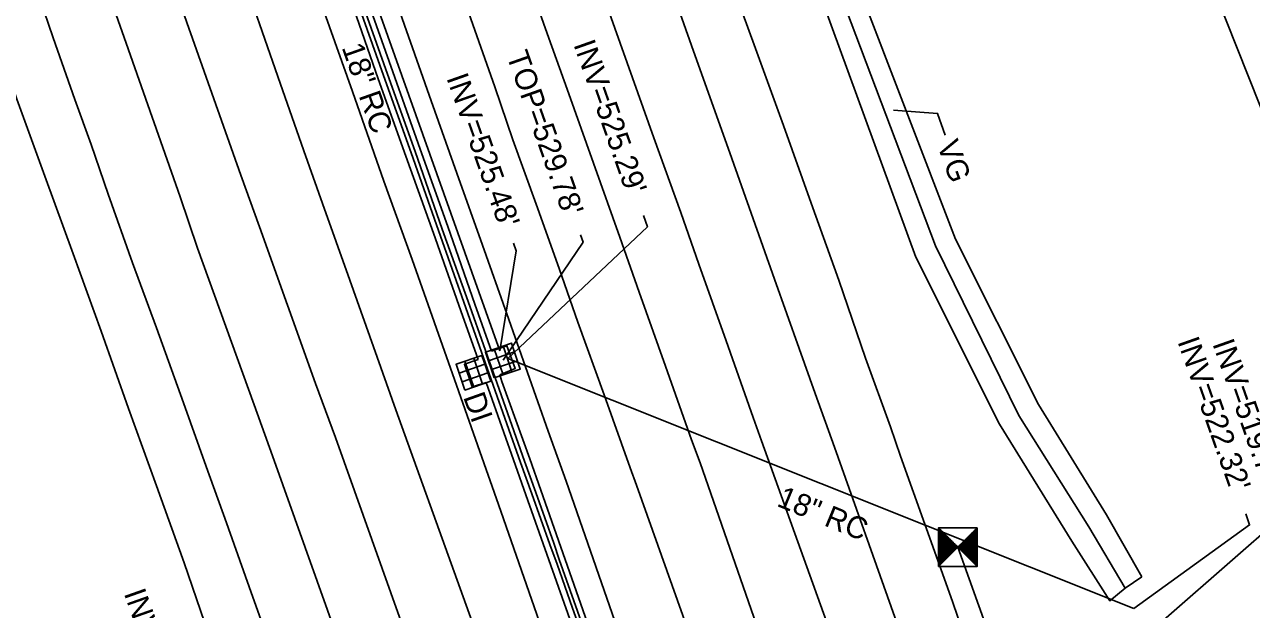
# Model space of a CAD drawing. Extents: x 2004847 to 2009016, y 1134161 to 1140101.
# Drawn here: x 2006823.5 to 2007047.7, y 1134296.2 to 1134403 of the extents above; entities that cross this region are included whole.
import ezdxf

# ---------------------------------------------------------------- set-up
doc = ezdxf.new("R2010")
doc.units = 0
for name, color, linetype in [('RD_EX_Conc', 7, 'Continuous'), ('RD_EX_DR_Inlet', 7, 'Continuous'), ('RD_EX_DR_Inlet_txCode', 7, 'Continuous'), ('RD_EX_DR_Pipe', 7, 'Continuous'), ('RD_EX_DR_Pipe_txCode', 7, 'Continuous'), ('RD_EX_Fence_Other', 7, 'Continuous'), ('RD_EX_Pavement_Markings', 7, 'Continuous'), ('RD_EX_Road', 7, 'Continuous'), ('RD_HC_Data', 7, 'Continuous'), ('RD_HC_Survey', 7, 'Continuous'), ('RD_Sketch1', 7, 'Continuous'), ('RD_Sketch3', 7, 'Continuous'), ('RD_SMD_Locator', 7, 'Continuous')]:
    doc.layers.add(name, color=color, linetype=linetype)

msp = doc.modelspace()

# ---------------------------------------------------------------- linework, layer by layer
at = {"layer": 'RD_EX_Conc'}
for points in [[(2007008.76, 1134333.65), (2006993.63, 1134363.82), (2006975.89, 1134409.97), (2006965.78, 1134441.02), (2006950.02, 1134485.15), (2006934.64, 1134528.55), (2006918.96, 1134572.55), (2006904.01, 1134614.93), (2006889.45, 1134656.34), (2006873.52, 1134701.79), (2006859.53, 1134740.78), (2006845, 1134783.14), (2006828.98, 1134829.04), (2006813.77, 1134872.83), (2006798.81, 1134915.62), (2006782.15, 1134963.38), (2006767.46, 1135005.24), (2006753.34, 1135046.25), (2006752.31, 1135048.89), (2006751.51, 1135051.2), (2006736.87, 1135093.18), (2006721.7, 1135136.82), (2006709.9, 1135170.59)], [(2007001.61, 1134330.02), (2006986.35, 1134360.57), (2006969.5, 1134406.75), (2006958.22, 1134438.26), (2006942.49, 1134482.23), (2006927.03, 1134526.16), (2006911.49, 1134569.75), (2006896.31, 1134613.04), (2006882.16, 1134653.08), (2006865.99, 1134699.12), (2006852.4, 1134738.21), (2006837.28, 1134781.15), (2006821.3, 1134826.88), (2006806.03, 1134870.56), (2006791.16, 1134913.28), (2006774.61, 1134960.65), (2006760.24, 1135002.17), (2006744.89, 1135045.85), (2006729.14, 1135091.12), (2006713.78, 1135134.81), (2006702.17, 1135168.35)], [(2006884.82, 1134408.14), (2006889.83, 1134394), (2006894.85, 1134379.86), (2006899.82, 1134365.69), (2006904.85, 1134351.58), (2006909.86, 1134337.45), (2006914.88, 1134323.3), (2006916.91, 1134317.58), (2006920.2, 1134308.31)], [(2006884.12, 1134407.89), (2006889.12, 1134393.75), (2006894.13, 1134379.6), (2006899.12, 1134365.44), (2006904.12, 1134351.32), (2006909.13, 1134337.19), (2006914.15, 1134323.04), (2006916.18, 1134317.32), (2006919.51, 1134308.07)], [(2007008.76, 1134333.65), (2007021.16, 1134313.47), (2007027.66, 1134302.15)], [(2007001.61, 1134330.02), (2007014.88, 1134308.67), (2007021.77, 1134297.8), (2007024.61, 1134300.06), (2007027.66, 1134302.15)], [(2006919.51, 1134308.07), (2006920.82, 1134304.45), (2006923.64, 1134296.45), (2006927.56, 1134285.43), (2006932.01, 1134272.71), (2006936.44, 1134260.24), (2006940.93, 1134247.46), (2006945.08, 1134236.09), (2006950.19, 1134222.05), (2006954.91, 1134209.27), (2006960.74, 1134193.25), (2006965.74, 1134179.46)], [(2006920.2, 1134308.31), (2006921.18, 1134305.31), (2006924.56, 1134295.87), (2006927.84, 1134286.59), (2006931.89, 1134275.31), (2006936.52, 1134262.16), (2006946.37, 1134234.52), (2006955.42, 1134209.78)]]:
    msp.add_lwpolyline(points, dxfattribs=at)
at = {"layer": 'RD_EX_DR_Inlet'}
for p, q in [((2006908.27, 1134341.62), (2006913, 1134343.24)), ((2006909.33, 1134343.78), (2006910.95, 1134339.05)), ((2006910.94, 1134344.33), (2006912.56, 1134339.6)), ((2006902.9, 1134339.39), (2006907.63, 1134341.01)), ((2006903.96, 1134341.55), (2006905.58, 1134336.82)), ((2006905.57, 1134342.1), (2006907.19, 1134337.37)), ((2006908.82, 1134340.01), (2006913.55, 1134341.63)), ((2006903.45, 1134337.78), (2006908.18, 1134339.4))]:
    msp.add_line(p, q, dxfattribs=at)
for points in [[(2006909.34, 1134338.5), (2006907.72, 1134343.23), (2006912.45, 1134344.85), (2006914.07, 1134340.12)], [(2006903.97, 1134336.27), (2006902.35, 1134341), (2006907.08, 1134342.62), (2006908.7, 1134337.89)]]:
    msp.add_lwpolyline(points, close=True, dxfattribs=at)
at = {"layer": 'RD_EX_DR_Inlet_txCode'}
for points in [[(2006911.82, 1134342.04), (2006937.31, 1134366.07), (2006936.58, 1134368.16)], [(2006910.37, 1134343.42), (2006913.32, 1134361.72), (2006912.82, 1134363.12)], [(2006910.95, 1134341.73), (2006925.58, 1134363.27), (2006925.1, 1134364.64)], [(2007026.17, 1134296.36), (2007047.34, 1134311.64), (2007046.63, 1134313.65)], [(2007026.17, 1134296.36), (2007047.34, 1134311.64), (2007046.63, 1134313.65)]]:
    msp.add_lwpolyline(points, dxfattribs=at)
at = {"layer": 'RD_EX_DR_Pipe'}
for p, q in [((2006876.41, 1134438.8), (2006910.37, 1134343.42)), ((2006911.82, 1134342.04), (2007026.17, 1134296.36))]:
    msp.add_line(p, q, dxfattribs=at)
at = {"layer": 'RD_EX_Fence_Other'}
msp.add_lwpolyline([(2007063.77, 1134349.09), (2007051.32, 1134382.98), (2007034.66, 1134424.99), (2007022.46, 1134465.49), (2007009.27, 1134502.08), (2006987.27, 1134565.71), (2006982.09, 1134580.37), (2006971.28, 1134619.61), (2006967.26, 1134636.51), (2006955.53, 1134679.01), (2006933.1, 1134763.45), (2006921.61, 1134808.45), (2006913.35, 1134838.48), (2006889.85, 1134911.88), (2006879.83, 1134940.33), (2006864.22, 1134985.13), (2006847.99, 1135029.35), (2006842.47, 1135045.23)], dxfattribs=at)
at = {"layer": 'RD_EX_Pavement_Markings'}
for points in [[(2006761.15, 1134736.06), (2006771.82, 1134705.98), (2006777.23, 1134690.59), (2006790.01, 1134654.11), (2006795.73, 1134638.12), (2006808.48, 1134602.29), (2006810.13, 1134597.78), (2006815.7, 1134582.21), (2006823.33, 1134560.46), (2006837.37, 1134520.96), (2006843.05, 1134504.9), (2006850.38, 1134484.11), (2006854.57, 1134472.19), (2006861.41, 1134452.78), (2006871.77, 1134423.99), (2006878.28, 1134405.4), (2006883.4, 1134390.84), (2006889.14, 1134374.45), (2006894.32, 1134360.11), (2006902.43, 1134337.19), (2006906.68, 1134325.03), (2006910.08, 1134315.38), (2006961.34, 1134168.46)], [(2006971.5, 1134325.84), (2006967.94, 1134335.67), (2006965.04, 1134343.86), (2006960.52, 1134356.54), (2006952.36, 1134379.64), (2006946.03, 1134397.35), (2006935.38, 1134427.48), (2006931.68, 1134438.01), (2006925.92, 1134454.61), (2006919.03, 1134473.64), (2006908.39, 1134503.37), (2006895.77, 1134538.71), (2006881.3, 1134579.46), (2006875.08, 1134597.59), (2006869.84, 1134612.25), (2006867.8, 1134618.04), (2006867.58, 1134618.64), (2006864.8, 1134626.66), (2006860.44, 1134639.08), (2006850.41, 1134667.47), (2006845.37, 1134681.65), (2006839.16, 1134699.2), (2006832.85, 1134717.15)], [(2006743.96, 1134712.87), (2006747.16, 1134703.49), (2006757.16, 1134675.58), (2006760.38, 1134666.33), (2006770.51, 1134637.87), (2006773.91, 1134628.44), (2006783.92, 1134600.29), (2006787.22, 1134590.86), (2006797.43, 1134562.07), (2006800.7, 1134552.91), (2006810.57, 1134524.57), (2006813.83, 1134515.22), (2006823.78, 1134487.36), (2006827.07, 1134477.97), (2006836.8, 1134450.28), (2006840.09, 1134440.58), (2006849.89, 1134412.94), (2006853.18, 1134403.45), (2006863.05, 1134375.55), (2006866.41, 1134366.09), (2006876.69, 1134337.46), (2006880.32, 1134327.63), (2006936.22, 1134170.67)], [(2006732.74, 1134708.5), (2006736.01, 1134699.34), (2006746.11, 1134671.03), (2006749.58, 1134661.19), (2006759.46, 1134633.21), (2006762.72, 1134624.11), (2006773.08, 1134595.66), (2006776.33, 1134586.35), (2006786.48, 1134557.89), (2006789.7, 1134548.67), (2006799.21, 1134521.6), (2006802.52, 1134512.03), (2006812.88, 1134483.28), (2006816.15, 1134473.85), (2006825.71, 1134446.36), (2006828.93, 1134437.07), (2006838.79, 1134409.05), (2006842.06, 1134399.64), (2006851.92, 1134371.56), (2006855.13, 1134362.22), (2006865.49, 1134333.56), (2006868.8, 1134324.26), (2006923.13, 1134171.83)], [(2006883.84, 1134428.74), (2006897.79, 1134389.14), (2006902.5, 1134375.87), (2006907.19, 1134362.72), (2006911.63, 1134350.18), (2006919.19, 1134328.78), (2006922.45, 1134319.62), (2006975.43, 1134167.21)], [(2006823.72, 1134415.28), (2006828.76, 1134400.65), (2006832.7, 1134389.34), (2006835.66, 1134381.11), (2006838.78, 1134372.04), (2006843.25, 1134359.55), (2006847.6, 1134347.64), (2006852.54, 1134333.93), (2006856.67, 1134322.33), (2006860.39, 1134312.05), (2006864.92, 1134299.29), (2006868.8, 1134288.39)], [(2006914.12, 1134415.17), (2006919.32, 1134400.58), (2006922.62, 1134391.27), (2006927.45, 1134377.74), (2006932.28, 1134364.2), (2006935.81, 1134354.15), (2006940.59, 1134340.67), (2006945.38, 1134327.18), (2006946.92, 1134322.99), (2007001.97, 1134164.87)], [(2006903.58, 1134408.31), (2006909.45, 1134391.65), (2006912.75, 1134381.99), (2006916.96, 1134370.24), (2006921.16, 1134358.49), (2006924.62, 1134348.7), (2006929.38, 1134335.39), (2006934.14, 1134322.08), (2006935.3, 1134318.88), (2006989.68, 1134165.96)], [(2006865.02, 1134407.18), (2006869.79, 1134393.58), (2006874.56, 1134379.97), (2006877.97, 1134370.37), (2006882.97, 1134356.33), (2006887.96, 1134342.28), (2006891.36, 1134332.69), (2006950.11, 1134169.45)], [(2006930.07, 1134405.96), (2006933.59, 1134396.06), (2006938.51, 1134382.38), (2006943.42, 1134368.71), (2006946.73, 1134359.26), (2006951.69, 1134345.27), (2006956.65, 1134331.28), (2006958.15, 1134327.03), (2007017, 1134163.54)], [(2006971.5, 1134325.84), (2006982.51, 1134294.78), (2006989.62, 1134274.68), (2006995.78, 1134257.27), (2007005.91, 1134228.34), (2007015.25, 1134201.92), (2007024.74, 1134174.73), (2007029.06, 1134162.48)]]:
    msp.add_lwpolyline(points, dxfattribs=at)
at = {"layer": 'RD_EX_Road'}
for points in [[(2006706.11, 1135169.52), (2006717.88, 1135136.12), (2006733.28, 1135092.09), (2006748.47, 1135047.58), (2006763.79, 1135003.81), (2006778.27, 1134961.83), (2006795.07, 1134914.22), (2006809.69, 1134871.89), (2006820.71, 1134840.68), (2006828.76, 1134817.54), (2006841.37, 1134782.12), (2006855.99, 1134739.87), (2006869.8, 1134700.59), (2006885.78, 1134654.79), (2006900.16, 1134613.89), (2006915.32, 1134570.8), (2006930.8, 1134527.38), (2006946.57, 1134483.83), (2006961.99, 1134439.72), (2006972.66, 1134408.4), (2006989.95, 1134362.61), (2007005.15, 1134331.63)], [(2006875.43, 1134437.82), (2006875.77, 1134436.81), (2006880.79, 1134422.7), (2006885.79, 1134408.56), (2006890.8, 1134394.42), (2006895.8, 1134380.27), (2006900.83, 1134366.13), (2006905.79, 1134351.99), (2006908.81, 1134343.37)], [(2006906.36, 1134341.89), (2006903.22, 1134350.76), (2006898.21, 1134364.93), (2006893.17, 1134379), (2006888.11, 1134393.13), (2006883.19, 1134407.29), (2006878.2, 1134421.43), (2006873.22, 1134435.63), (2006872.87, 1134436.63)], [(2006951.94, 1134412.74), (2006957.06, 1134398.69), (2006962.2, 1134384.6), (2006967.23, 1134370.42), (2006972.26, 1134356.33), (2006977.16, 1134342.12), (2006981.75, 1134329.57)], [(2006817.28, 1134403.67), (2006822.12, 1134389.44), (2006827.23, 1134375.38), (2006832.39, 1134361.16), (2006837.52, 1134347.01), (2006842.51, 1134332.9), (2006847.61, 1134318.79), (2006852.69, 1134304.74), (2006855.68, 1134296.02), (2006859.43, 1134284.98)], [(2006908.81, 1134343.37), (2006911.61, 1134344.36), (2006913.15, 1134340.23), (2006910.32, 1134339.06)], [(2006907.86, 1134337.68), (2006905.28, 1134336.84), (2006903.87, 1134340.98), (2006906.36, 1134341.89)], [(2006910.32, 1134339.06), (2006910.74, 1134337.83), (2006915.85, 1134323.72), (2006917.85, 1134317.98), (2006932.84, 1134275.32)], [(2006940.98, 1134244.01), (2006915.11, 1134317.17), (2006913.22, 1134322.48), (2006908.23, 1134336.6), (2006907.86, 1134337.68)], [(2006981.75, 1134329.57), (2006983.57, 1134324.23), (2006993.04, 1134297.64), (2007003.84, 1134266), (2007009.98, 1134249.28), (2007027.62, 1134199.49), (2007039.25, 1134168.02), (2007041.62, 1134161.37)], [(2007005.15, 1134331.63), (2007017.95, 1134311.28), (2007024.61, 1134300.06)]]:
    msp.add_lwpolyline(points, dxfattribs=at)
at = {"layer": 'RD_HC_Data'}
msp.add_line((2006994.03, 1134307.6), (2007027.82, 1134213.17), dxfattribs=at)
at = {"layer": 'RD_HC_Survey'}
for p, q in [((2006990.5, 1134311.14), (2006997.57, 1134304.07)), ((2006997.57, 1134311.14), (2006990.5, 1134304.07)), ((2006990.55, 1134311.09), (2006990.55, 1134304.12)), ((2006990.6, 1134311.04), (2006990.6, 1134304.17)), ((2006990.65, 1134310.99), (2006990.65, 1134304.22)), ((2006990.7, 1134310.94), (2006990.7, 1134304.27)), ((2006990.75, 1134310.89), (2006990.75, 1134304.32)), ((2006990.8, 1134310.84), (2006990.8, 1134304.37)), ((2006990.85, 1134310.79), (2006990.85, 1134304.42)), ((2006990.9, 1134310.74), (2006990.9, 1134304.47)), ((2006990.95, 1134310.69), (2006990.95, 1134304.52)), ((2006991, 1134310.64), (2006991, 1134304.57)), ((2006991.05, 1134310.59), (2006991.05, 1134304.62)), ((2006991.1, 1134310.54), (2006991.1, 1134304.67)), ((2006991.15, 1134310.49), (2006991.15, 1134304.72)), ((2006991.2, 1134310.44), (2006991.2, 1134304.77)), ((2006991.25, 1134310.39), (2006991.25, 1134304.82)), ((2006991.3, 1134310.34), (2006991.3, 1134304.87)), ((2006991.35, 1134310.29), (2006991.35, 1134304.92)), ((2006991.4, 1134310.24), (2006991.4, 1134304.97)), ((2006991.45, 1134310.19), (2006991.45, 1134305.02)), ((2006991.5, 1134310.14), (2006991.5, 1134305.07)), ((2006991.55, 1134310.09), (2006991.55, 1134305.12)), ((2006991.6, 1134310.04), (2006991.6, 1134305.17)), ((2006991.65, 1134309.99), (2006991.65, 1134305.22)), ((2006991.7, 1134309.94), (2006991.7, 1134305.27)), ((2006991.75, 1134309.89), (2006991.75, 1134305.32)), ((2006991.8, 1134309.84), (2006991.8, 1134305.37)), ((2006991.85, 1134309.79), (2006991.85, 1134305.42)), ((2006991.9, 1134309.74), (2006991.9, 1134305.47)), ((2006991.95, 1134309.69), (2006991.95, 1134305.52)), ((2006992, 1134309.64), (2006992, 1134305.57)), ((2006992.05, 1134309.59), (2006992.05, 1134305.62)), ((2006992.1, 1134309.54), (2006992.1, 1134305.67)), ((2006992.15, 1134309.49), (2006992.15, 1134305.72)), ((2006992.2, 1134309.44), (2006992.2, 1134305.77)), ((2006992.25, 1134309.39), (2006992.25, 1134305.82)), ((2006992.3, 1134309.34), (2006992.3, 1134305.87)), ((2006995.77, 1134309.34), (2006995.77, 1134305.87)), ((2006995.82, 1134309.39), (2006995.82, 1134305.82)), ((2006995.87, 1134309.44), (2006995.87, 1134305.77)), ((2006995.92, 1134309.49), (2006995.92, 1134305.72)), ((2006995.97, 1134309.54), (2006995.97, 1134305.67)), ((2006996.02, 1134309.59), (2006996.02, 1134305.62)), ((2006996.07, 1134309.64), (2006996.07, 1134305.57)), ((2006996.12, 1134309.69), (2006996.12, 1134305.52)), ((2006996.17, 1134309.74), (2006996.17, 1134305.47)), ((2006996.22, 1134309.79), (2006996.22, 1134305.42)), ((2006996.27, 1134309.84), (2006996.27, 1134305.37)), ((2006996.32, 1134309.89), (2006996.32, 1134305.32)), ((2006996.37, 1134309.94), (2006996.37, 1134305.27)), ((2006996.42, 1134309.99), (2006996.42, 1134305.22)), ((2006996.47, 1134310.04), (2006996.47, 1134305.17)), ((2006996.52, 1134310.09), (2006996.52, 1134305.12)), ((2006996.57, 1134310.14), (2006996.57, 1134305.07)), ((2006996.62, 1134310.19), (2006996.62, 1134305.02)), ((2006996.67, 1134310.24), (2006996.67, 1134304.97)), ((2006996.72, 1134310.29), (2006996.72, 1134304.92)), ((2006996.77, 1134310.34), (2006996.77, 1134304.87)), ((2006996.82, 1134310.39), (2006996.82, 1134304.82)), ((2006996.87, 1134310.44), (2006996.87, 1134304.77)), ((2006996.92, 1134310.49), (2006996.92, 1134304.72)), ((2006996.97, 1134310.54), (2006996.97, 1134304.67)), ((2006997.02, 1134310.59), (2006997.02, 1134304.62)), ((2006997.07, 1134310.64), (2006997.07, 1134304.57)), ((2006997.12, 1134310.69), (2006997.12, 1134304.52)), ((2006997.17, 1134310.74), (2006997.17, 1134304.47)), ((2006997.22, 1134310.79), (2006997.22, 1134304.42)), ((2006997.27, 1134310.84), (2006997.27, 1134304.37)), ((2006997.32, 1134310.89), (2006997.32, 1134304.32)), ((2006997.37, 1134310.94), (2006997.37, 1134304.27)), ((2006997.42, 1134310.99), (2006997.42, 1134304.22)), ((2006997.47, 1134311.04), (2006997.47, 1134304.17)), ((2006997.52, 1134311.09), (2006997.52, 1134304.12)), ((2006992.35, 1134309.29), (2006992.35, 1134305.92)), ((2006992.4, 1134309.24), (2006992.4, 1134305.97)), ((2006992.45, 1134309.19), (2006992.45, 1134306.02)), ((2006992.5, 1134309.14), (2006992.5, 1134306.07)), ((2006992.55, 1134309.09), (2006992.55, 1134306.12)), ((2006992.6, 1134309.04), (2006992.6, 1134306.17)), ((2006992.65, 1134308.99), (2006992.65, 1134306.22)), ((2006992.7, 1134308.94), (2006992.7, 1134306.27)), ((2006992.75, 1134308.89), (2006992.75, 1134306.32)), ((2006992.8, 1134308.84), (2006992.8, 1134306.37)), ((2006992.85, 1134308.79), (2006992.85, 1134306.42)), ((2006992.9, 1134308.74), (2006992.9, 1134306.47)), ((2006992.95, 1134308.69), (2006992.95, 1134306.52)), ((2006993, 1134308.64), (2006993, 1134306.57)), ((2006993.05, 1134308.59), (2006993.05, 1134306.62)), ((2006993.1, 1134308.54), (2006993.1, 1134306.67)), ((2006993.15, 1134308.49), (2006993.15, 1134306.72)), ((2006993.2, 1134308.44), (2006993.2, 1134306.77)), ((2006993.25, 1134308.39), (2006993.25, 1134306.82)), ((2006993.3, 1134308.34), (2006993.3, 1134306.87)), ((2006993.35, 1134308.29), (2006993.35, 1134306.92)), ((2006993.4, 1134308.24), (2006993.4, 1134306.97)), ((2006993.45, 1134308.19), (2006993.45, 1134307.02)), ((2006993.5, 1134308.14), (2006993.5, 1134307.07)), ((2006993.55, 1134308.09), (2006993.55, 1134307.12)), ((2006993.6, 1134308.04), (2006993.6, 1134307.17)), ((2006993.65, 1134307.99), (2006993.65, 1134307.22)), ((2006993.7, 1134307.94), (2006993.7, 1134307.27)), ((2006993.75, 1134307.89), (2006993.75, 1134307.32)), ((2006993.8, 1134307.84), (2006993.8, 1134307.37)), ((2006993.85, 1134307.79), (2006993.85, 1134307.42)), ((2006993.9, 1134307.74), (2006993.9, 1134307.47)), ((2006993.95, 1134307.69), (2006993.95, 1134307.52)), ((2006994, 1134307.64), (2006994, 1134307.57)), ((2006994.07, 1134307.64), (2006994.07, 1134307.57)), ((2006994.12, 1134307.69), (2006994.12, 1134307.52)), ((2006994.17, 1134307.74), (2006994.17, 1134307.47)), ((2006994.22, 1134307.79), (2006994.22, 1134307.42)), ((2006994.27, 1134307.84), (2006994.27, 1134307.37)), ((2006994.32, 1134307.89), (2006994.32, 1134307.32)), ((2006994.37, 1134307.94), (2006994.37, 1134307.27)), ((2006994.42, 1134307.99), (2006994.42, 1134307.22)), ((2006994.47, 1134308.04), (2006994.47, 1134307.17)), ((2006994.52, 1134308.09), (2006994.52, 1134307.12)), ((2006994.57, 1134308.14), (2006994.57, 1134307.07)), ((2006994.62, 1134308.19), (2006994.62, 1134307.02)), ((2006994.67, 1134308.24), (2006994.67, 1134306.97)), ((2006994.72, 1134308.29), (2006994.72, 1134306.92)), ((2006994.77, 1134308.34), (2006994.77, 1134306.87)), ((2006994.82, 1134308.39), (2006994.82, 1134306.82)), ((2006994.87, 1134308.44), (2006994.87, 1134306.77)), ((2006994.92, 1134308.49), (2006994.92, 1134306.72)), ((2006994.97, 1134308.54), (2006994.97, 1134306.67)), ((2006995.02, 1134308.59), (2006995.02, 1134306.62)), ((2006995.07, 1134308.64), (2006995.07, 1134306.57)), ((2006995.12, 1134308.69), (2006995.12, 1134306.52)), ((2006995.17, 1134308.74), (2006995.17, 1134306.47)), ((2006995.22, 1134308.79), (2006995.22, 1134306.42)), ((2006995.27, 1134308.84), (2006995.27, 1134306.37)), ((2006995.32, 1134308.89), (2006995.32, 1134306.32)), ((2006995.37, 1134308.94), (2006995.37, 1134306.27)), ((2006995.42, 1134308.99), (2006995.42, 1134306.22)), ((2006995.47, 1134309.04), (2006995.47, 1134306.17)), ((2006995.52, 1134309.09), (2006995.52, 1134306.12)), ((2006995.57, 1134309.14), (2006995.57, 1134306.07)), ((2006995.62, 1134309.19), (2006995.62, 1134306.02)), ((2006995.67, 1134309.24), (2006995.67, 1134305.97)), ((2006995.72, 1134309.29), (2006995.72, 1134305.92))]:
    msp.add_line(p, q, dxfattribs=at)
msp.add_lwpolyline([(2006997.57, 1134311.14), (2006990.5, 1134311.14), (2006990.5, 1134304.07), (2006997.57, 1134304.07)], close=True, dxfattribs=at)
at = {"layer": 'RD_Sketch1'}
for points in [[(2007022.9, 1134286.65), (2007053.4, 1134313.31), (2007052.46, 1134315.98)], [(2007026.17, 1134296.36), (2007047.34, 1134311.64), (2007046.63, 1134313.65)]]:
    msp.add_lwpolyline(points, dxfattribs=at)
at = {"layer": 'RD_Sketch3'}
msp.add_lwpolyline([(2006991.73, 1134382.87), (2006990.34, 1134386.8), (2006982.3, 1134387.42)], dxfattribs=at)
at = {"layer": 'RD_SMD_Locator'}
msp.add_circle((2006994.03, 1134307.6), 0.15, dxfattribs=at)

# ---------------------------------------------------------------- texts
at = {"layer": 'RD_EX_DR_Inlet_txCode'}
for s, p in [("INV=525.29'", (2006923.76, 1134399.42)), ("TOP=529.78'", (2006911.51, 1134397.43)), ("INV=525.48'", (2006900.55, 1134393.31)), ("INV=522.32'", (2007034.11, 1134345.16)), ("INV=522.32'", (2007034.11, 1134345.16)), ('DI', (2006903.61, 1134335.03))]:
    msp.add_text(s, height=4, rotation=289.4494, dxfattribs=at).set_placement(p)
at = {"layer": 'RD_EX_DR_Pipe_txCode'}
for rotation, p in [(289.4494, (2006881.42, 1134398.88)), (337.6634, (2006960.77, 1134315.16)), (337.6634, (2006960.77, 1134315.16))]:
    msp.add_text('18" RC', height=4, rotation=rotation, dxfattribs=at).set_placement(p)
at = {"layer": 'RD_Sketch1'}
for s, p in [("INV=522.32'", (2007034.11, 1134345.16)), ("INV=519.79'", (2007040.5, 1134344.76)), ("INV=521.37'", (2006841.62, 1134299.16))]:
    msp.add_text(s, height=4, rotation=289.4494, dxfattribs=at).set_placement(p)
at = {"layer": 'RD_Sketch3'}
msp.add_text('VG', height=4, rotation=289.4494, dxfattribs=at).set_placement((2006990.2, 1134381.11))

doc.saveas('drawing.dxf')
